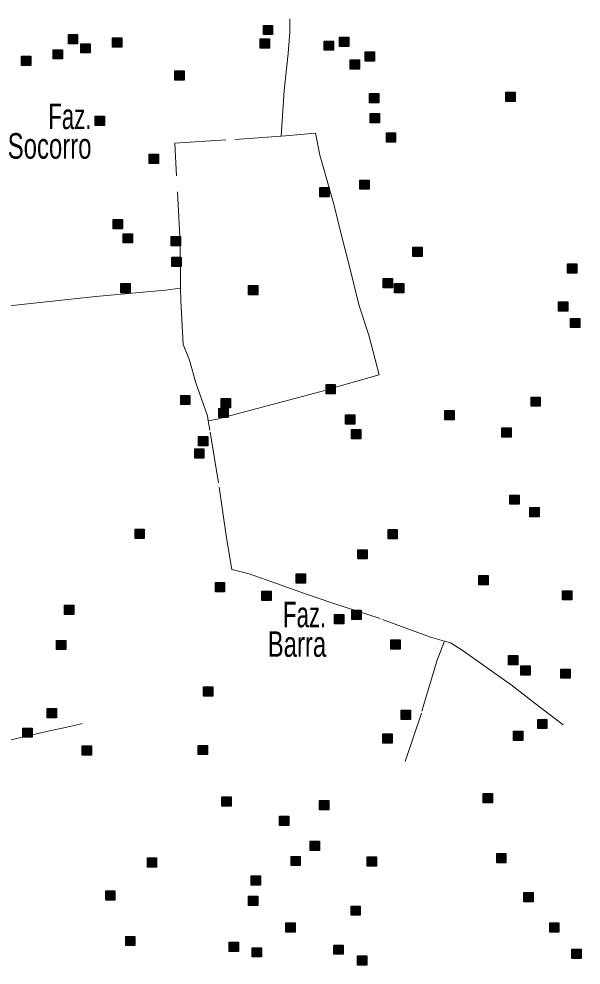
# Model space of a CAD drawing. Extents: x 445.6 to 500, y 8618.1 to 8673.4.
# Drawn here: x 493.89 to 497.41, y 8667.5 to 8673.43 of the extents above; entities that cross this region are included whole.
import ezdxf
from ezdxf.enums import TextEntityAlignment as Align

# ---------------------------------------------------------------- set-up
doc = ezdxf.new("R2010")
doc.units = 0
doc.header["$LTSCALE"] = 0.064
doc.linetypes.add('DOT_DASHED', pattern=[7.7, 5, -1.2, 0.3, -1.2])
doc.layers.add('2', color=7, linetype='Continuous', lineweight=25)
doc.layers.add('22', color=7, linetype='DOT_DASHED', lineweight=13)
doc.layers.add('61', color=7, linetype='Continuous')

msp = doc.modelspace()

# ---------------------------------------------------------------- hatches: boundary and pattern name
at = {"layer": '2'}
for points in [[(495.4201, 8673.3905), (495.4781, 8673.3905), (495.4781, 8673.3325), (495.4201, 8673.3325)], [(494.1992, 8673.3329), (494.2572, 8673.3329), (494.2572, 8673.2749), (494.1992, 8673.2749)], [(494.4762, 8673.3126), (494.5342, 8673.3126), (494.5342, 8673.2546), (494.4762, 8673.2546)], [(495.3999, 8673.3058), (495.4579, 8673.3058), (495.4579, 8673.2478), (495.3999, 8673.2478)], [(495.8018, 8673.2923), (495.8598, 8673.2923), (495.8598, 8673.2343), (495.8018, 8673.2343)], [(495.8964, 8673.316), (495.9544, 8673.316), (495.9544, 8673.258), (495.8964, 8673.258)], [(494.1046, 8673.238), (494.1626, 8673.238), (494.1626, 8673.18), (494.1046, 8673.18)], [(494.2769, 8673.2753), (494.3349, 8673.2753), (494.3349, 8673.2173), (494.2769, 8673.2173)], [(493.9053, 8673.1974), (493.9633, 8673.1974), (493.9633, 8673.1394), (493.9053, 8673.1394)], [(495.964, 8673.1737), (496.022, 8673.1737), (496.022, 8673.1157), (495.964, 8673.1157)], [(496.0585, 8673.2245), (496.1165, 8673.2245), (496.1165, 8673.1665), (496.0585, 8673.1665)], [(494.8662, 8673.1059), (494.9242, 8673.1059), (494.9242, 8673.0479), (494.8662, 8673.0479)], [(496.0856, 8672.9637), (496.1436, 8672.9637), (496.1436, 8672.9057), (496.0856, 8672.9057)], [(496.9381, 8672.9709), (496.9961, 8672.9709), (496.9961, 8672.9129), (496.9381, 8672.9129)], [(494.3681, 8672.8213), (494.4261, 8672.8213), (494.4261, 8672.7633), (494.3681, 8672.7633)], [(496.0889, 8672.8383), (496.1469, 8672.8383), (496.1469, 8672.7803), (496.0889, 8672.7803)], [(496.1903, 8672.7163), (496.2483, 8672.7163), (496.2483, 8672.6583), (496.1903, 8672.6583)], [(494.7058, 8672.5841), (494.7638, 8672.5841), (494.7638, 8672.5261), (494.7058, 8672.5261)], [(496.0248, 8672.4216), (496.0828, 8672.4216), (496.0828, 8672.3636), (496.0248, 8672.3636)], [(495.7748, 8672.3741), (495.8328, 8672.3741), (495.8328, 8672.3161), (495.7748, 8672.3161)], [(494.4795, 8672.1742), (494.5375, 8672.1742), (494.5375, 8672.1162), (494.4795, 8672.1162)], [(494.5433, 8672.0854), (494.6013, 8672.0854), (494.6013, 8672.0274), (494.5433, 8672.0274)], [(494.8435, 8672.0683), (494.9015, 8672.0683), (494.9015, 8672.0103), (494.8435, 8672.0103)], [(496.3556, 8672.001), (496.4136, 8672.001), (496.4136, 8671.943), (496.3556, 8671.943)], [(494.8469, 8671.9383), (494.9049, 8671.9383), (494.9049, 8671.8803), (494.8469, 8671.8803)], [(497.325, 8671.896), (497.383, 8671.896), (497.383, 8671.838), (497.325, 8671.838)], [(494.5276, 8671.774), (494.5856, 8671.774), (494.5856, 8671.716), (494.5276, 8671.716)], [(495.3281, 8671.7605), (495.3861, 8671.7605), (495.3861, 8671.7025), (495.3281, 8671.7025)], [(496.1708, 8671.8045), (496.2288, 8671.8045), (496.2288, 8671.7465), (496.1708, 8671.7465)], [(496.2417, 8671.774), (496.2997, 8671.774), (496.2997, 8671.716), (496.2417, 8671.716)], [(497.2676, 8671.6588), (497.3256, 8671.6588), (497.3256, 8671.6008), (497.2676, 8671.6008)], [(497.3432, 8671.5551), (497.4012, 8671.5551), (497.4012, 8671.4971), (497.3432, 8671.4971)], [(495.8127, 8671.1404), (495.8707, 8671.1404), (495.8707, 8671.0824), (495.8127, 8671.0824)], [(494.9025, 8671.0727), (494.9605, 8671.0727), (494.9605, 8671.0147), (494.9025, 8671.0147)], [(495.1559, 8671.0524), (495.2139, 8671.0524), (495.2139, 8670.9944), (495.1559, 8670.9944)], [(497.0963, 8671.0625), (497.1543, 8671.0625), (497.1543, 8671.0045), (497.0963, 8671.0045)], [(495.1424, 8670.9914), (495.2004, 8670.9914), (495.2004, 8670.9334), (495.1424, 8670.9334)], [(495.9344, 8670.9507), (495.9924, 8670.9507), (495.9924, 8670.8927), (495.9344, 8670.8927)], [(496.5559, 8670.9778), (496.6139, 8670.9778), (496.6139, 8670.9198), (496.5559, 8670.9198)], [(496.9129, 8670.8694), (496.9709, 8670.8694), (496.9709, 8670.8114), (496.9129, 8670.8114)], [(495.014, 8670.8152), (495.072, 8670.8152), (495.072, 8670.7572), (495.014, 8670.7572)], [(495.9715, 8670.8592), (496.0295, 8670.8592), (496.0295, 8670.8012), (495.9715, 8670.8012)], [(494.9903, 8670.7373), (495.0483, 8670.7373), (495.0483, 8670.6793), (494.9903, 8670.6793)], [(496.9641, 8670.4486), (497.0221, 8670.4486), (497.0221, 8670.3906), (496.9641, 8670.3906)], [(497.0891, 8670.3707), (497.1471, 8670.3707), (497.1471, 8670.3127), (497.0891, 8670.3127)], [(494.6166, 8670.2352), (494.6746, 8670.2352), (494.6746, 8670.1772), (494.6166, 8670.1772)], [(496.2008, 8670.2318), (496.2588, 8670.2318), (496.2588, 8670.1738), (496.2008, 8670.1738)], [(496.0116, 8670.1064), (496.0696, 8670.1064), (496.0696, 8670.0484), (496.0116, 8670.0484)], [(495.6264, 8669.9546), (495.6844, 8669.9546), (495.6844, 8669.8966), (495.6264, 8669.8966)], [(496.7696, 8669.9445), (496.8276, 8669.9445), (496.8276, 8669.8865), (496.7696, 8669.8865)], [(495.1197, 8669.9004), (495.1777, 8669.9004), (495.1777, 8669.8424), (495.1197, 8669.8424)], [(495.4102, 8669.8462), (495.4682, 8669.8462), (495.4682, 8669.7882), (495.4102, 8669.7882)], [(497.2932, 8669.8496), (497.3512, 8669.8496), (497.3512, 8669.7916), (497.2932, 8669.7916)], [(494.1751, 8669.7584), (494.2331, 8669.7584), (494.2331, 8669.7004), (494.1751, 8669.7004)], [(495.8662, 8669.7005), (495.9242, 8669.7005), (495.9242, 8669.6425), (495.8662, 8669.6425)], [(495.9743, 8669.7276), (496.0323, 8669.7276), (496.0323, 8669.6696), (495.9743, 8669.6696)], [(494.1245, 8669.5381), (494.1825, 8669.5381), (494.1825, 8669.4801), (494.1245, 8669.4801)], [(496.2191, 8669.5417), (496.2771, 8669.5417), (496.2771, 8669.4837), (496.2191, 8669.4837)], [(496.9554, 8669.4435), (497.0134, 8669.4435), (497.0134, 8669.3855), (496.9554, 8669.3855)], [(497.0331, 8669.3791), (497.0911, 8669.3791), (497.0911, 8669.3211), (497.0331, 8669.3211)], [(497.2831, 8669.3588), (497.3411, 8669.3588), (497.3411, 8669.3008), (497.2831, 8669.3008)], [(495.0454, 8669.2465), (495.1034, 8669.2465), (495.1034, 8669.1885), (495.0454, 8669.1885)], [(494.0671, 8669.1112), (494.1251, 8669.1112), (494.1251, 8669.0532), (494.0671, 8669.0532)], [(496.2832, 8669.1013), (496.3412, 8669.1013), (496.3412, 8669.0433), (496.2832, 8669.0433)], [(497.1378, 8669.0437), (497.1958, 8669.0437), (497.1958, 8668.9857), (497.1378, 8668.9857)], [(493.9151, 8668.9893), (493.9731, 8668.9893), (493.9731, 8668.9313), (493.9151, 8668.9313)], [(496.9858, 8668.9691), (497.0438, 8668.9691), (497.0438, 8668.9111), (496.9858, 8668.9111)], [(496.1684, 8668.9522), (496.2264, 8668.9522), (496.2264, 8668.8942), (496.1684, 8668.8942)], [(494.2855, 8668.8775), (494.3435, 8668.8775), (494.3435, 8668.8195), (494.2855, 8668.8195)], [(495.0116, 8668.8806), (495.0696, 8668.8806), (495.0696, 8668.8226), (495.0116, 8668.8226)], [(495.1603, 8668.5588), (495.2183, 8668.5588), (495.2183, 8668.5008), (495.1603, 8668.5008)], [(496.7967, 8668.5795), (496.8547, 8668.5795), (496.8547, 8668.5215), (496.7967, 8668.5215)], [(495.7716, 8668.535), (495.8296, 8668.535), (495.8296, 8668.477), (495.7716, 8668.477)], [(495.5217, 8668.4368), (495.5797, 8668.4368), (495.5797, 8668.3788), (495.5217, 8668.3788)], [(495.7142, 8668.2809), (495.7722, 8668.2809), (495.7722, 8668.2229), (495.7142, 8668.2229)], [(496.8811, 8668.2034), (496.9391, 8668.2034), (496.9391, 8668.1454), (496.8811, 8668.1454)], [(494.6941, 8668.1759), (494.7521, 8668.1759), (494.7521, 8668.1179), (494.6941, 8668.1179)], [(495.5936, 8668.1856), (495.6516, 8668.1856), (495.6516, 8668.1276), (495.5936, 8668.1276)], [(496.0698, 8668.1822), (496.1278, 8668.1822), (496.1278, 8668.1242), (496.0698, 8668.1242)], [(495.3436, 8668.0636), (495.4016, 8668.0636), (495.4016, 8668.0056), (495.3436, 8668.0056)], [(494.4333, 8667.969), (494.4913, 8667.969), (494.4913, 8667.911), (494.4333, 8667.911)], [(497.0508, 8667.9586), (497.1088, 8667.9586), (497.1088, 8667.9006), (497.0508, 8667.9006)], [(495.3272, 8667.9352), (495.3852, 8667.9352), (495.3852, 8667.8772), (495.3272, 8667.8772)], [(495.969, 8667.8742), (496.027, 8667.8742), (496.027, 8667.8162), (495.969, 8667.8162)], [(495.5603, 8667.7691), (495.6183, 8667.7691), (495.6183, 8667.7111), (495.5603, 8667.7111)], [(497.2129, 8667.7693), (497.2709, 8667.7693), (497.2709, 8667.7113), (497.2129, 8667.7113)], [(494.5583, 8667.6844), (494.6163, 8667.6844), (494.6163, 8667.6264), (494.5583, 8667.6264)], [(495.2056, 8667.6472), (495.2636, 8667.6472), (495.2636, 8667.5892), (495.2056, 8667.5892)], [(495.3509, 8667.6133), (495.4089, 8667.6133), (495.4089, 8667.5553), (495.3509, 8667.5553)], [(495.8609, 8667.6302), (495.9189, 8667.6302), (495.9189, 8667.5722), (495.8609, 8667.5722)], [(497.3514, 8667.6033), (497.4094, 8667.6033), (497.4094, 8667.5453), (497.3514, 8667.5453)], [(496.0095, 8667.5625), (496.0675, 8667.5625), (496.0675, 8667.5045), (496.0095, 8667.5045)]]:
    msp.add_hatch(color=256, dxfattribs=at).paths.add_polyline_path(points)

# ---------------------------------------------------------------- linework, layer by layer
for points in [[(495.4201, 8673.3905), (495.4781, 8673.3905), (495.4781, 8673.3325), (495.4201, 8673.3325)], [(494.1992, 8673.3329), (494.2572, 8673.3329), (494.2572, 8673.2749), (494.1992, 8673.2749)], [(494.4762, 8673.3126), (494.5342, 8673.3126), (494.5342, 8673.2546), (494.4762, 8673.2546)], [(495.3999, 8673.3058), (495.4579, 8673.3058), (495.4579, 8673.2478), (495.3999, 8673.2478)], [(495.8018, 8673.2923), (495.8598, 8673.2923), (495.8598, 8673.2343), (495.8018, 8673.2343)], [(495.8964, 8673.316), (495.9544, 8673.316), (495.9544, 8673.258), (495.8964, 8673.258)], [(494.1046, 8673.238), (494.1626, 8673.238), (494.1626, 8673.18), (494.1046, 8673.18)], [(494.2769, 8673.2753), (494.3349, 8673.2753), (494.3349, 8673.2173), (494.2769, 8673.2173)], [(493.9053, 8673.1974), (493.9633, 8673.1974), (493.9633, 8673.1394), (493.9053, 8673.1394)], [(495.964, 8673.1737), (496.022, 8673.1737), (496.022, 8673.1157), (495.964, 8673.1157)], [(496.0585, 8673.2245), (496.1165, 8673.2245), (496.1165, 8673.1665), (496.0585, 8673.1665)], [(494.8662, 8673.1059), (494.9242, 8673.1059), (494.9242, 8673.0479), (494.8662, 8673.0479)], [(496.0856, 8672.9637), (496.1436, 8672.9637), (496.1436, 8672.9057), (496.0856, 8672.9057)], [(496.9381, 8672.9709), (496.9961, 8672.9709), (496.9961, 8672.9129), (496.9381, 8672.9129)], [(494.3681, 8672.8213), (494.4261, 8672.8213), (494.4261, 8672.7633), (494.3681, 8672.7633)], [(496.0889, 8672.8383), (496.1469, 8672.8383), (496.1469, 8672.7803), (496.0889, 8672.7803)], [(496.1903, 8672.7163), (496.2483, 8672.7163), (496.2483, 8672.6583), (496.1903, 8672.6583)], [(494.7058, 8672.5841), (494.7638, 8672.5841), (494.7638, 8672.5261), (494.7058, 8672.5261)], [(496.0248, 8672.4216), (496.0828, 8672.4216), (496.0828, 8672.3636), (496.0248, 8672.3636)], [(495.7748, 8672.3741), (495.8328, 8672.3741), (495.8328, 8672.3161), (495.7748, 8672.3161)], [(494.4795, 8672.1742), (494.5375, 8672.1742), (494.5375, 8672.1162), (494.4795, 8672.1162)], [(494.5433, 8672.0854), (494.6013, 8672.0854), (494.6013, 8672.0274), (494.5433, 8672.0274)], [(494.8435, 8672.0683), (494.9015, 8672.0683), (494.9015, 8672.0103), (494.8435, 8672.0103)], [(496.3556, 8672.001), (496.4136, 8672.001), (496.4136, 8671.943), (496.3556, 8671.943)], [(494.8469, 8671.9383), (494.9049, 8671.9383), (494.9049, 8671.8803), (494.8469, 8671.8803)], [(497.325, 8671.896), (497.383, 8671.896), (497.383, 8671.838), (497.325, 8671.838)], [(494.5276, 8671.774), (494.5856, 8671.774), (494.5856, 8671.716), (494.5276, 8671.716)], [(495.3281, 8671.7605), (495.3861, 8671.7605), (495.3861, 8671.7025), (495.3281, 8671.7025)], [(496.1708, 8671.8045), (496.2288, 8671.8045), (496.2288, 8671.7465), (496.1708, 8671.7465)], [(496.2417, 8671.774), (496.2997, 8671.774), (496.2997, 8671.716), (496.2417, 8671.716)], [(497.2676, 8671.6588), (497.3256, 8671.6588), (497.3256, 8671.6008), (497.2676, 8671.6008)], [(497.3432, 8671.5551), (497.4012, 8671.5551), (497.4012, 8671.4971), (497.3432, 8671.4971)], [(495.8127, 8671.1404), (495.8707, 8671.1404), (495.8707, 8671.0824), (495.8127, 8671.0824)], [(494.9025, 8671.0727), (494.9605, 8671.0727), (494.9605, 8671.0147), (494.9025, 8671.0147)], [(495.1559, 8671.0524), (495.2139, 8671.0524), (495.2139, 8670.9944), (495.1559, 8670.9944)], [(497.0963, 8671.0625), (497.1543, 8671.0625), (497.1543, 8671.0045), (497.0963, 8671.0045)], [(495.1424, 8670.9914), (495.2004, 8670.9914), (495.2004, 8670.9334), (495.1424, 8670.9334)], [(495.9344, 8670.9507), (495.9924, 8670.9507), (495.9924, 8670.8927), (495.9344, 8670.8927)], [(496.5559, 8670.9778), (496.6139, 8670.9778), (496.6139, 8670.9198), (496.5559, 8670.9198)], [(496.9129, 8670.8694), (496.9709, 8670.8694), (496.9709, 8670.8114), (496.9129, 8670.8114)], [(495.014, 8670.8152), (495.072, 8670.8152), (495.072, 8670.7572), (495.014, 8670.7572)], [(495.9715, 8670.8592), (496.0295, 8670.8592), (496.0295, 8670.8012), (495.9715, 8670.8012)], [(494.9903, 8670.7373), (495.0483, 8670.7373), (495.0483, 8670.6793), (494.9903, 8670.6793)], [(496.9641, 8670.4486), (497.0221, 8670.4486), (497.0221, 8670.3906), (496.9641, 8670.3906)], [(497.0891, 8670.3707), (497.1471, 8670.3707), (497.1471, 8670.3127), (497.0891, 8670.3127)], [(494.6166, 8670.2352), (494.6746, 8670.2352), (494.6746, 8670.1772), (494.6166, 8670.1772)], [(496.2008, 8670.2318), (496.2588, 8670.2318), (496.2588, 8670.1738), (496.2008, 8670.1738)], [(496.0116, 8670.1064), (496.0696, 8670.1064), (496.0696, 8670.0484), (496.0116, 8670.0484)], [(495.6264, 8669.9546), (495.6844, 8669.9546), (495.6844, 8669.8966), (495.6264, 8669.8966)], [(496.7696, 8669.9445), (496.8276, 8669.9445), (496.8276, 8669.8865), (496.7696, 8669.8865)], [(495.1197, 8669.9004), (495.1777, 8669.9004), (495.1777, 8669.8424), (495.1197, 8669.8424)], [(495.4102, 8669.8462), (495.4682, 8669.8462), (495.4682, 8669.7882), (495.4102, 8669.7882)], [(497.2932, 8669.8496), (497.3512, 8669.8496), (497.3512, 8669.7916), (497.2932, 8669.7916)], [(494.1751, 8669.7584), (494.2331, 8669.7584), (494.2331, 8669.7004), (494.1751, 8669.7004)], [(495.8662, 8669.7005), (495.9242, 8669.7005), (495.9242, 8669.6425), (495.8662, 8669.6425)], [(495.9743, 8669.7276), (496.0323, 8669.7276), (496.0323, 8669.6696), (495.9743, 8669.6696)], [(494.1245, 8669.5381), (494.1825, 8669.5381), (494.1825, 8669.4801), (494.1245, 8669.4801)], [(496.2191, 8669.5417), (496.2771, 8669.5417), (496.2771, 8669.4837), (496.2191, 8669.4837)], [(496.9554, 8669.4435), (497.0134, 8669.4435), (497.0134, 8669.3855), (496.9554, 8669.3855)], [(497.0331, 8669.3791), (497.0911, 8669.3791), (497.0911, 8669.3211), (497.0331, 8669.3211)], [(497.2831, 8669.3588), (497.3411, 8669.3588), (497.3411, 8669.3008), (497.2831, 8669.3008)], [(495.0454, 8669.2465), (495.1034, 8669.2465), (495.1034, 8669.1885), (495.0454, 8669.1885)], [(494.0671, 8669.1112), (494.1251, 8669.1112), (494.1251, 8669.0532), (494.0671, 8669.0532)], [(496.2832, 8669.1013), (496.3412, 8669.1013), (496.3412, 8669.0433), (496.2832, 8669.0433)], [(497.1378, 8669.0437), (497.1958, 8669.0437), (497.1958, 8668.9857), (497.1378, 8668.9857)], [(493.9151, 8668.9893), (493.9731, 8668.9893), (493.9731, 8668.9313), (493.9151, 8668.9313)], [(496.9858, 8668.9691), (497.0438, 8668.9691), (497.0438, 8668.9111), (496.9858, 8668.9111)], [(496.1684, 8668.9522), (496.2264, 8668.9522), (496.2264, 8668.8942), (496.1684, 8668.8942)], [(494.2855, 8668.8775), (494.3435, 8668.8775), (494.3435, 8668.8195), (494.2855, 8668.8195)], [(495.0116, 8668.8806), (495.0696, 8668.8806), (495.0696, 8668.8226), (495.0116, 8668.8226)], [(495.1603, 8668.5588), (495.2183, 8668.5588), (495.2183, 8668.5008), (495.1603, 8668.5008)], [(496.7967, 8668.5795), (496.8547, 8668.5795), (496.8547, 8668.5215), (496.7967, 8668.5215)], [(495.7716, 8668.535), (495.8296, 8668.535), (495.8296, 8668.477), (495.7716, 8668.477)], [(495.5217, 8668.4368), (495.5797, 8668.4368), (495.5797, 8668.3788), (495.5217, 8668.3788)], [(495.7142, 8668.2809), (495.7722, 8668.2809), (495.7722, 8668.2229), (495.7142, 8668.2229)], [(496.8811, 8668.2034), (496.9391, 8668.2034), (496.9391, 8668.1454), (496.8811, 8668.1454)], [(494.6941, 8668.1759), (494.7521, 8668.1759), (494.7521, 8668.1179), (494.6941, 8668.1179)], [(495.5936, 8668.1856), (495.6516, 8668.1856), (495.6516, 8668.1276), (495.5936, 8668.1276)], [(496.0698, 8668.1822), (496.1278, 8668.1822), (496.1278, 8668.1242), (496.0698, 8668.1242)], [(495.3436, 8668.0636), (495.4016, 8668.0636), (495.4016, 8668.0056), (495.3436, 8668.0056)], [(494.4333, 8667.969), (494.4913, 8667.969), (494.4913, 8667.911), (494.4333, 8667.911)], [(497.0508, 8667.9586), (497.1088, 8667.9586), (497.1088, 8667.9006), (497.0508, 8667.9006)], [(495.3272, 8667.9352), (495.3852, 8667.9352), (495.3852, 8667.8772), (495.3272, 8667.8772)], [(495.969, 8667.8742), (496.027, 8667.8742), (496.027, 8667.8162), (495.969, 8667.8162)], [(495.5603, 8667.7691), (495.6183, 8667.7691), (495.6183, 8667.7111), (495.5603, 8667.7111)], [(497.2129, 8667.7693), (497.2709, 8667.7693), (497.2709, 8667.7113), (497.2129, 8667.7113)], [(494.5583, 8667.6844), (494.6163, 8667.6844), (494.6163, 8667.6264), (494.5583, 8667.6264)], [(495.2056, 8667.6472), (495.2636, 8667.6472), (495.2636, 8667.5892), (495.2056, 8667.5892)], [(495.3509, 8667.6133), (495.4089, 8667.6133), (495.4089, 8667.5553), (495.3509, 8667.5553)], [(495.8609, 8667.6302), (495.9189, 8667.6302), (495.9189, 8667.5722), (495.8609, 8667.5722)], [(497.3514, 8667.6033), (497.4094, 8667.6033), (497.4094, 8667.5453), (497.3514, 8667.5453)], [(496.0095, 8667.5625), (496.0675, 8667.5625), (496.0675, 8667.5045), (496.0095, 8667.5045)]]:
    msp.add_lwpolyline(points, close=True, dxfattribs=at)
at = {"layer": '22'}
for points in [[(495.5315, 8672.6957), (495.5503, 8672.9833), (495.5757, 8673.2133), (495.5863, 8673.3484), (495.5856, 8673.4307)], [(495.5315, 8672.6957), (495.5582, 8672.6975), (495.7463, 8672.7157), (495.7736, 8672.5763), (495.8616, 8672.2702), (495.9112, 8672.0661), (495.9536, 8671.9055), (496.0204, 8671.6327), (496.0813, 8671.4497), (496.145, 8671.2012), (495.8052, 8671.1042), (495.5461, 8671.0334), (495.2488, 8670.9547), (495.1305, 8670.9243), (495.0755, 8670.9137)], [(494.9021, 8671.7438), (494.8997, 8672.029), (494.8724, 8672.5278), (494.8664, 8672.652), (495.2426, 8672.6763), (495.5315, 8672.6957)], [(492.6489, 8671.9853), (492.8151, 8671.8852), (493.0214, 8671.7811), (493.2863, 8671.6445), (493.3688, 8671.5946), (493.6098, 8671.6184), (493.8096, 8671.6314), (494.0606, 8671.6597), (494.3711, 8671.6922), (494.6447, 8671.7182), (494.8076, 8671.7312), (494.9021, 8671.7438)], [(495.0755, 8670.9137), (495.0702, 8670.9453), (494.9974, 8671.1514), (494.958, 8671.2938), (494.9185, 8671.3908), (494.9028, 8671.6654), (494.9021, 8671.7438)], [(496.5539, 8669.5339), (496.4676, 8669.5592), (496.152, 8669.6743), (495.8547, 8669.7713), (495.6773, 8669.8329), (495.474, 8669.9057), (495.3314, 8669.9541), (495.2221, 8669.9814), (495.1888, 8670.1814), (495.1401, 8670.5258), (495.0854, 8670.8544), (495.0755, 8670.9137)], [(496.3084, 8668.7796), (496.4131, 8669.0944), (496.5052, 8669.4046), (496.5539, 8669.5339)], [(497.2972, 8669.0099), (497.1139, 8669.1501), (496.9804, 8669.2531), (496.771, 8669.4016), (496.6587, 8669.4804), (496.592, 8669.5228), (496.5539, 8669.5339)], [(492.0274, 8667.6587), (491.9683, 8668.0205), (491.9483, 8668.1254), (492.2035, 8668.1918), (492.6708, 8668.3116), (492.9032, 8668.379), (493.1256, 8668.4289), (493.2131, 8668.5587), (493.3197, 8668.7423), (493.3497, 8668.8097), (493.5672, 8668.8521), (493.8221, 8668.912), (494.0545, 8668.9644), (494.2369, 8669.0044), (494.2867, 8669.0185)]]:
    msp.add_lwpolyline(points, dxfattribs=at)

# ---------------------------------------------------------------- texts
at = {"layer": '61'}
for s, width, p in [('Faz.', 0.65, (494.344, 8672.7403)), ('Socorro', 0.7, (494.344, 8672.5553)), ('Faz.', 0.65, (495.8136, 8669.6204)), ('Barra', 0.7, (495.8136, 8669.4354))]:
    msp.add_text(s, height=0.16, dxfattribs=dict(at, width=width)).set_placement(p, align=Align.RIGHT)

doc.saveas('drawing.dxf')
